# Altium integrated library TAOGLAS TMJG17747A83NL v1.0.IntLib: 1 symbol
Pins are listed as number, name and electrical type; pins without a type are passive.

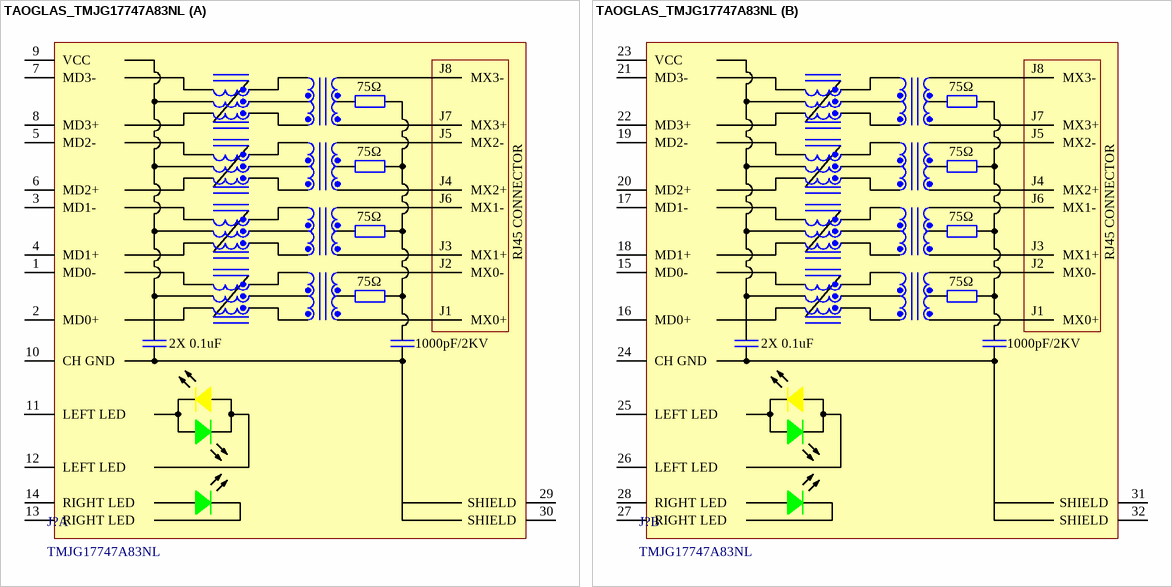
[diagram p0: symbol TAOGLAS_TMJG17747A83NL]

## TAOGLAS_TMJG17747A83NL
designator J?, comment TMJG17747A83NL
RJ45 connector with integrated magnetics 1G Base-T. Dual Stack Port THT mount and LEDs.; ComponentLibStatus: Created; MFG: Taoglas; Temp_High: +85C; Temp_Low: -40C
footprint TAOGLAS_TMJG17747A83NL (RJ45 connector with integrated magnetics 1G Base-T. Dual Stack Port THT mount and LEDs.)
part A pins: 1 MD0-, 2 MD0+, 3 MD1-, 4 MD1+, 5 MD2-, 6 MD2+, 7 MD3-, 8 MD3+, 9 VCC, 10 CH GND, 11 LEFT LED, 12 LEFT LED, 13 RIGHT LED, 14 RIGHT LED, 29 SHIELD, 30 SHIELD
part B pins: 15 MD0-, 16 MD0+, 17 MD1-, 18 MD1+, 19 MD2-, 20 MD2+, 21 MD3-, 22 MD3+, 23 VCC, 24 CH GND, 25 LEFT LED, 26 LEFT LED, 27 RIGHT LED, 28 RIGHT LED, 31 SHIELD, 32 SHIELD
